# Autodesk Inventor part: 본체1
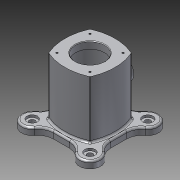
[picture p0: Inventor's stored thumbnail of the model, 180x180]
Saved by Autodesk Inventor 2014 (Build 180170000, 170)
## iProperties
Created: 2016-05
Part Number: 본체1
Material: 알루미늄 6061
Document SubType Name: Modeling
Designer: Administrator
Density: 2.71 g/cm^3
Appearance: 알루미늄 - 평지
Mass: 1111.1 g
Surface Area: 865.598 cm^2
Volume: 409.999 cm^3
Author: Administrator
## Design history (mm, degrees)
sketch "스케치1" dims "d1" = 70
  geometry: L1 (-49, 49)-(49, 49); L2 (49, 49)-(49, -49); L3 (49, -49)-(-49, -49); L4 (-49, -49)-(-49, 49); L5 (0, 0)-(-49.497, 49.497); L6 (0, 0)-(0, 49); C1 r 18 at (-49.497, 49.497); C2 r 18 at (-49.497, -49.497); C3 r 18 at (49.497, -49.497); C4 r 18 at (49.497, 49.497); 2 further points
  constraints: 12 end point, 4 centre point, 3 parallel, 2 midpoint, 1 coincident, 1 horizontal, 1 horizontal alignment, 1 perpendicular, 1 vertical alignment, 12 other
  dimensions: "d2" = 98 distance of L2.end L3.end; "d3" = 98 distance of L1.end L2.end; "d4" = 45 deg angle of L5 L6; "d6" = 18 radius of C1; "d9" = 360 deg dimension on point (0, 0) L5.end (derived)
extrude "돌출1" new body sketch "스케치1" distance "d11" = 12; taper "d12" = 0 deg
hole "구멍1" diameter "d15" = 10; stored, may be unused: countersink angle "d19" = 90 deg, drill point angle "d21" = 118 deg; dims "d13" = 10, "d14" = 10, "d16" = 6, "d17" = 18, "d18" = 4, "d20" = 8
fillet "모깎기1" dims "d28" = 25
sketch "스케치2"
  geometry: L1 (0, 0)-(-28.284, 28.284); L2 (0, 0)-(0, 40); A1 r 40 centre (0, 0) between (0, 40) and (-28.284, 28.284); 2 further points
  constraints: 4 end point, 2 coincident, 2 point on circle, 1 centre point
  dimensions: "d31" = 40 radius of A1; "d32" = 45 deg angle of L2 L1
hole "구멍2" sketch "스케치2" at (-28.284, 28.284) diameter "d33" = 3.242; stored, may be unused: countersink angle "d37" = 90 deg, drill point angle "d39" = 120 deg; dims "d34" = 7, "d35" = 18, "d36" = 4, "d38" = 10
sketch "스케치3"
  geometry: L1 (-43, 43)-(43, 43); L2 (43, 43)-(43, -43); L3 (43, -43)-(-43, -43); L4 (-43, -43)-(-43, 43); L5 (-35.355, 35.355)-(35.355, 35.355); L6 (35.355, 35.355)-(35.355, -35.355); L7 (35.355, -35.355)-(-35.355, -35.355); L8 (-35.355, -35.355)-(-35.355, 35.355); L9 (0, 0)-(-43, 43); L10 (0, 0)-(43, 43); A1 r 85.963 centre (43, 0) between (-35.355, 35.355) and (-35.355, -35.355); A2 r 85.579 centre (0, -42.579) between (35.355, 35.355) and (-35.355, 35.355); A3 r 85.579 centre (-42.579, 0) between (35.355, -35.355) and (35.355, 35.355); A4 r 85.579 centre (0, 42.579) between (-35.355, -35.355) and (35.355, -35.355); 4 further points
  constraints: 20 end point, 11 point on circle, 4 centre point, 4 midpoint, 4 parallel, 2 horizontal, 2 horizontal alignment, 2 perpendicular, 2 vertical alignment, 1 point on line, 1 tangent
  dimensions: "d75" = 86 distance between parallel lines of L4 L2; "d76" = 86 distance between parallel lines of L3 L1; "d78" = 100 distance of L7.end L5.end
extrude "돌출2" join sketch "스케치3" distance "d79" = 98; taper "d80" = 0 deg
sketch "스케치4"
  geometry: 2 further points
  constraints: 1 coincident
hole "구멍3" sketch "스케치4" at (0, 0) diameter "d81" = 50; stored, may be unused: countersink angle "d85" = 90 deg, drill point angle "d87" = 120 deg; dims "d82" = 50, "d83" = 18, "d84" = 4, "d86" = 10
sketch "스케치5"
  geometry: L1 (35, 98)-(0, 98); L2 (0, 98)-(0, 12); L3 (0, 12)-(35, 12); L4 (35, 12)-(35, 98); L5 (-25, 110)-(25, 110) reference; L6 (25, 0)-(-25, 0) reference; L7 (0, 110)-(0, 98); 1 further point
  constraints: 10 end point, 2 parallel, 2 perpendicular, 1 horizontal, 1 midpoint, 1 vertical alignment
  dimensions: "d88" = 70 diameter of L4 L2; "d89" = 12 distance between parallel lines of L5 L1; "d90" = 12 distance between parallel lines of L6 L3
revolve "회전1" sketch "스케치5" stored, may be unused: angle "d91" = 90 deg
sketch "스케치6"
  geometry: L1 (0, 0)-(28.284, 28.284); L2 (0, 0)-(0, 40); C1 r 25 at (0, 0) reference; A1 r 40 centre (0, 0) between (0, 40) and (28.284, 28.284); 1 further point
  constraints: 4 end point, 2 coincident, 2 point on circle, 1 centre point, 1 vertical
  dimensions: "d92" = 40 radius of A1; "d93" = 45 deg angle of L1 L2
hole "구멍4" sketch "스케치6" at (28.284, 28.284) diameter "d94" = 3.242; stored, may be unused: countersink angle "d98" = 90 deg, drill point angle "d100" = 120 deg; dims "d95" = 7, "d96" = 18, "d97" = 4, "d99" = 10
node "작업 평면1"
sketch "스케치7"
  geometry: L1 (0, -22)-(0, 132) reference; L2 (35.355, 110)-(-35.355, 110) reference; C1 r 20 at (0, 61); 1 further point
  constraints: 1 centre point, 1 point on line
  dimensions: "d109" = 40 diameter of C1; "d112" = 49 distance from line of C1.centre L2
extrude "돌출3" join sketch "스케치7" stored distance "d110" = 98; taper "d111" = 10 deg
hole "구멍5" diameter "d115" = 25; stored, may be unused: countersink angle "d119" = 90 deg, drill point angle "d121" = 120 deg; dims "d113" = 10, "d114" = 10, "d116" = 7, "d117" = 30, "d118" = 8, "d120" = 10
node "작업 평면3"
sketch "스케치9"
  geometry: L1 (35.355, 98)-(-35.355, 98) reference; C1 r 12.5 at (0, 49) reference; 2 further points
  constraints: 1 other
  dimensions: "d126" = 29 distance of point (-29, 49) C1.centre; "d127" = 49 distance from line of L1 point (-29, 49)
feature "엠보싱2" sketch "스케치9" dims "d1" = 70, "d2" = 98, "d3" = 98, "d4" = 45 deg, "d6" = 18, "d9" = 360 deg (derived), "d128" = 0.5, "d129" = 0
fillet "모깎기2" dims "d130" = 3
fillet "모깎기3" dims "d131" = 3
fillet "모깎기4" dims "d132" = 3
chamfer "모따기1" distance "d133" = 1; stored, may be unused: second distance "d134" = 2, angle "d135" = 45 deg
node "솔리드1"
pattern_circular "원형 패턴1" dims angle "d102" = 360 deg
pattern_circular "원형 패턴2" dims angle "d105" = 360 deg
pattern_circular "원형 패턴3" dims angle "d137" = 360 deg
other parameters: "d107" = 55
